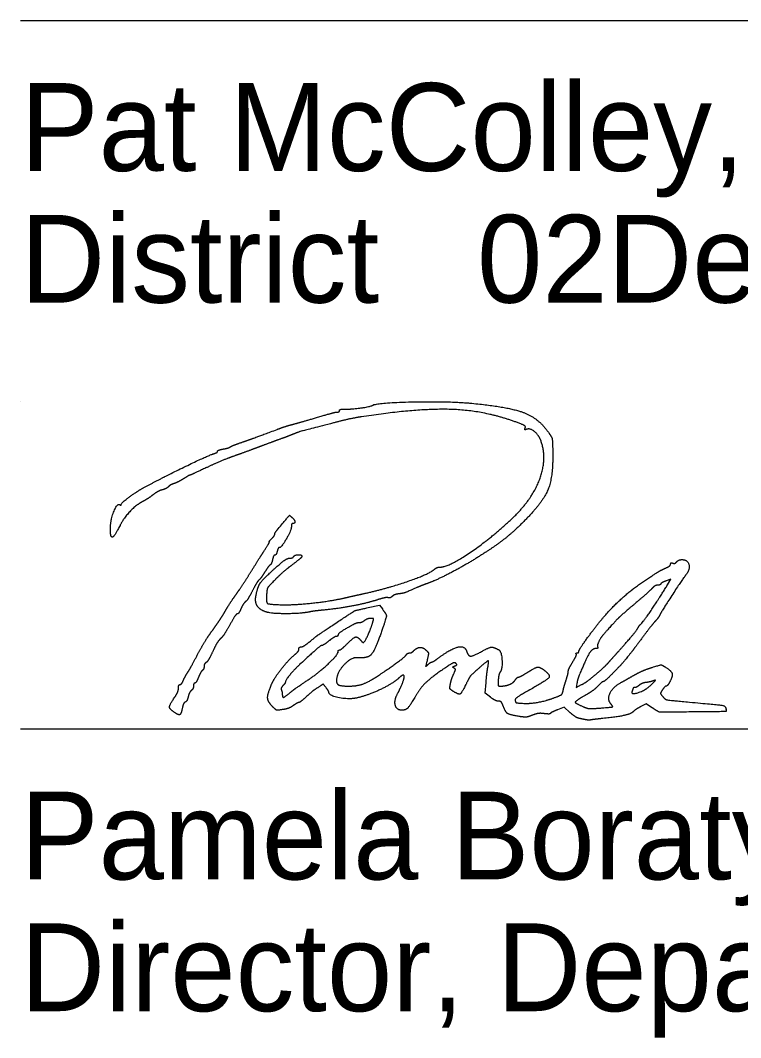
# Model space of a CAD drawing. Extents: x 0 to 42, y 0 to 22.
# Drawn here: x 24.528 to 25.676, y 7.305 to 8.926 of the extents above; entities that cross this region are included whole.
import ezdxf

# ---------------------------------------------------------------- set-up
doc = ezdxf.new("R2010")
doc.units = 0
doc.layers.add('SH_Data', color=7, linetype='Continuous')
doc.layers.add('SH_Text', color=7, linetype='Continuous')

msp = doc.modelspace()

# ---------------------------------------------------------------- linework, layer by layer
at = {"layer": 'SH_Data'}
for p, q in [((24.5279, 8.9262), (28.0279, 8.9262)), ((24.5279, 8.3191), (24.5279, 8.3191)), ((24.5279, 7.7968), (28.0279, 7.7968))]:
    msp.add_line(p, q, dxfattribs=at)
at = {"layer": 'SH_Text'}
for points in [[(25.5597, 8.0263), (25.5651, 8.0352), (25.5577, 8.0326)], [(25.0824, 7.9901), (25.1004, 7.9942), (25.1051, 7.988)], [(25.2773, 7.8473), (25.269, 7.8536), (25.2704, 7.8707)], [(25.4153, 7.8693), (25.4143, 7.8628), (25.4229, 7.8673)], [(25.5361, 7.83), (25.5255, 7.8368), (25.5171, 7.8323)], [(25.4043, 7.823), (25.3951, 7.8313), (25.3845, 7.8272)]]:
    msp.add_lwpolyline(points, dxfattribs=at)
for points in [[(25.033, 8.3018), (25.0351, 8.3018), (25.0368, 8.3029), (25.0368, 8.3043)], [(25.0368, 8.3043), (25.0368, 8.3056), (25.0408, 8.3066), (25.0458, 8.3065)], [(25.0458, 8.3065), (25.0554, 8.3062), (25.0864, 8.3106), (25.0898, 8.3127)], [(25.3205, 8.285), (25.2699, 8.304), (25.1619, 8.308), (25.0716, 8.2942)], [(25.0898, 8.3127), (25.0966, 8.3169), (25.2136, 8.3192), (25.248, 8.3158)], [(25.248, 8.3158), (25.3072, 8.31), (25.3548, 8.2917), (25.3706, 8.2686)], [(24.9612, 8.282), (24.9665, 8.2833), (24.9839, 8.2883), (25, 8.2931)], [(25, 8.2931), (25.0161, 8.2979), (25.031, 8.3018), (25.033, 8.3018)], [(25.0716, 8.2942), (25.0623, 8.2928), (25.0424, 8.2885), (25.0272, 8.2845)], [(24.8808, 8.2535), (24.8955, 8.2586), (24.9019, 8.261), (24.9372, 8.2741)], [(24.9372, 8.2741), (24.9451, 8.2771), (24.9559, 8.2806), (24.9612, 8.282)], [(25.0272, 8.2845), (24.9762, 8.2714), (24.9719, 8.2701), (24.9612, 8.2658)], [(25.3328, 8.2764), (25.3338, 8.2789), (25.3303, 8.2813), (25.3205, 8.285)], [(25.3352, 8.2743), (25.3326, 8.2733), (25.3319, 8.274), (25.3328, 8.2764)], [(25.3586, 8.2544), (25.3553, 8.2642), (25.3409, 8.2765), (25.3352, 8.2743)], [(24.9384, 8.2573), (24.9285, 8.2537), (24.9134, 8.2481), (24.9048, 8.2449)], [(24.9612, 8.2658), (24.9585, 8.2647), (24.9483, 8.2609), (24.9384, 8.2573)], [(25.3131, 8.1332), (25.344, 8.1627), (25.3679, 8.2262), (25.3586, 8.2544)], [(25.3706, 8.2686), (25.3755, 8.2614), (25.3764, 8.257), (25.3768, 8.2392)], [(24.837, 8.2357), (24.84, 8.2366), (24.8424, 8.2382), (24.8424, 8.2393)], [(24.8424, 8.2393), (24.8424, 8.2403), (24.8464, 8.242), (24.8514, 8.2429)], [(24.8514, 8.2429), (24.8563, 8.2438), (24.8615, 8.2454), (24.8628, 8.2464)], [(24.8628, 8.2464), (24.8641, 8.2473), (24.8722, 8.2506), (24.8808, 8.2535)], [(24.9048, 8.2449), (24.8962, 8.2416), (24.88, 8.2357), (24.8688, 8.2317)], [(25.3768, 8.2392), (25.3775, 8.1984), (25.3614, 8.1587), (25.332, 8.1288)], [(24.7248, 8.1814), (24.755, 8.1976), (24.8286, 8.2333), (24.837, 8.2357)], [(24.8688, 8.2317), (24.8576, 8.2278), (24.8372, 8.2192), (24.8236, 8.2127)], [(24.8236, 8.2127), (24.8099, 8.2063), (24.7983, 8.201), (24.7977, 8.201)], [(24.7877, 8.1953), (24.7828, 8.1922), (24.7761, 8.1888), (24.7729, 8.1878)], [(24.7977, 8.201), (24.7971, 8.201), (24.7927, 8.1984), (24.7877, 8.1953)], [(24.6888, 8.1547), (24.6888, 8.1569), (24.7142, 8.1757), (24.7248, 8.1814)], [(24.754, 8.1778), (24.7505, 8.1769), (24.7438, 8.1733), (24.7392, 8.1697)], [(24.7637, 8.1826), (24.7619, 8.1808), (24.7576, 8.1787), (24.754, 8.1778)], [(24.7729, 8.1878), (24.7697, 8.1868), (24.7655, 8.1844), (24.7637, 8.1826)], [(24.7233, 8.1594), (24.7129, 8.1541), (24.693, 8.1332), (24.6868, 8.1211)], [(24.7392, 8.1697), (24.7346, 8.1661), (24.7274, 8.1615), (24.7233, 8.1594)], [(24.6716, 8.1169), (24.6717, 8.1301), (24.6823, 8.1567), (24.6865, 8.1541)], [(24.6865, 8.1541), (24.6877, 8.1533), (24.6888, 8.1536), (24.6888, 8.1547)], [(24.939, 8.1158), (24.9575, 8.1379), (24.9568, 8.1374), (24.9609, 8.134)], [(24.9609, 8.134), (24.9652, 8.1304), (24.9661, 8.1242), (24.9624, 8.1242)], [(25.1964, 8.0546), (25.2105, 8.0546), (25.2786, 8.1005), (25.3131, 8.1332)], [(25.332, 8.1288), (25.3134, 8.1099), (25.281, 8.085), (25.2505, 8.0662)], [(24.673, 8.1032), (24.6722, 8.104), (24.6716, 8.1101), (24.6716, 8.1169)], [(24.6868, 8.1211), (24.6801, 8.1082), (24.6748, 8.1013), (24.673, 8.1032)], [(24.9336, 8.1072), (24.9336, 8.1084), (24.936, 8.1123), (24.939, 8.1158)], [(24.96, 8.1191), (24.96, 8.1135), (24.9441, 8.0858), (24.9409, 8.0858)], [(24.9624, 8.1242), (24.9611, 8.1242), (24.96, 8.1219), (24.96, 8.1191)], [(24.916, 8.0797), (24.9216, 8.0883), (24.9256, 8.0954), (24.925, 8.0954)], [(24.925, 8.0954), (24.9245, 8.0954), (24.9261, 8.0975), (24.9288, 8.1002)], [(24.9288, 8.1002), (24.9314, 8.1028), (24.9336, 8.1059), (24.9336, 8.1072)], [(24.894, 8.0447), (24.9006, 8.0553), (24.9105, 8.0711), (24.916, 8.0797)], [(24.9374, 8.0798), (24.9366, 8.0765), (24.9349, 8.0738), (24.9337, 8.0738)], [(24.9409, 8.0858), (24.9398, 8.0858), (24.9382, 8.0831), (24.9374, 8.0798)], [(24.9252, 8.0448), (24.9409, 8.0594), (24.9536, 8.069), (24.9576, 8.069)], [(24.93, 8.0666), (24.9291, 8.0626), (24.9274, 8.0588), (24.9261, 8.058)], [(24.9337, 8.0738), (24.9325, 8.0738), (24.9309, 8.0705), (24.93, 8.0666)], [(24.9576, 8.069), (24.9601, 8.069), (24.9628, 8.07), (24.9636, 8.0714)], [(24.9768, 8.0717), (24.9768, 8.0706), (24.97, 8.0647), (24.9618, 8.0586)], [(24.9636, 8.0714), (24.9654, 8.0743), (24.9768, 8.0746), (24.9768, 8.0717)], [(25.2505, 8.0662), (25.2313, 8.0543), (25.1901, 8.0333), (25.176, 8.0282)], [(25.5648, 8.0595), (25.5648, 8.061), (25.5663, 8.0617), (25.5682, 8.061)], [(25.5682, 8.061), (25.5701, 8.0602), (25.5729, 8.0612), (25.5745, 8.0631)], [(25.5745, 8.0631), (25.5761, 8.065), (25.5798, 8.0666), (25.5827, 8.0666)], [(25.5827, 8.0666), (25.5921, 8.0666), (25.5959, 8.0505), (25.5885, 8.0415)], [(24.8722, 8.0117), (24.8776, 8.0192), (24.8874, 8.034), (24.894, 8.0447)], [(24.9038, 8.0102), (24.9066, 8.0232), (24.9127, 8.0332), (24.9252, 8.0448)], [(24.9176, 8.0466), (24.9142, 8.0411), (24.9101, 8.0355), (24.9084, 8.0341)], [(24.9261, 8.058), (24.9248, 8.0572), (24.921, 8.0521), (24.9176, 8.0466)], [(24.9618, 8.0586), (24.9535, 8.0525), (24.941, 8.0416), (24.934, 8.0345)], [(25.0764, 8.0126), (25.1133, 8.0208), (25.1796, 8.0437), (25.1882, 8.0512)], [(25.1882, 8.0512), (25.1903, 8.0531), (25.1939, 8.0546), (25.1964, 8.0546)], [(25.528, 8.0362), (25.5469, 8.0484), (25.5488, 8.0495), (25.557, 8.0532)], [(25.557, 8.0532), (25.5613, 8.0551), (25.5648, 8.058), (25.5648, 8.0595)], [(24.9084, 8.0341), (24.9068, 8.0328), (24.9021, 8.0252), (24.8981, 8.0172)], [(24.934, 8.0345), (24.9233, 8.0235), (24.9211, 8.0199), (24.9206, 8.0116)], [(25.176, 8.0282), (25.1714, 8.0266), (25.1643, 8.0238), (25.1603, 8.022)], [(25.4334, 7.9437), (25.4556, 7.9745), (25.5007, 8.0185), (25.528, 8.0362)], [(25.549, 8.0279), (25.5483, 8.0267), (25.5459, 8.0258), (25.5437, 8.0258)], [(25.5885, 8.0415), (25.5843, 8.0365), (25.5515, 7.9861), (25.5483, 7.9799)], [(25.5577, 8.0326), (25.5537, 8.0312), (25.5498, 8.0291), (25.549, 8.0279)], [(24.8555, 7.9862), (24.8593, 7.9928), (24.8669, 8.0043), (24.8722, 8.0117)], [(24.8981, 8.0172), (24.8941, 8.0092), (24.889, 8.0012), (24.8868, 7.9994)], [(24.9206, 8.0116), (24.9197, 7.9982), (24.9238, 7.9953), (24.9444, 7.9947)], [(25.0428, 8.0051), (25.0507, 8.0069), (25.0658, 8.0103), (25.0764, 8.0126)], [(25.1318, 8.0121), (25.1279, 8.0117), (25.123, 8.0099), (25.121, 8.0081)], [(25.1603, 8.022), (25.1433, 8.0146), (25.1384, 8.0129), (25.1318, 8.0121)], [(25.5349, 8.0204), (25.5322, 8.0174), (25.5197, 8.0063), (25.5072, 7.9958)], [(25.5169, 7.9634), (25.5197, 7.9653), (25.5479, 8.0068), (25.5597, 8.0263)], [(25.5437, 8.0258), (25.5415, 8.0258), (25.5375, 8.0233), (25.5349, 8.0204)], [(24.8868, 7.9994), (24.8847, 7.9976), (24.8814, 7.9925), (24.8796, 7.9881)], [(24.9192, 7.9833), (24.9087, 7.9872), (24.9016, 7.9997), (24.9038, 8.0102)], [(24.9444, 7.9947), (24.9636, 7.9942), (25.0215, 8.0003), (25.0428, 8.0051)], [(25.0962, 8.0022), (25.0797, 7.9969), (25.0346, 7.9884), (25.0108, 7.9861)], [(25.1142, 8.0059), (25.1125, 8.0065), (25.1044, 8.0048), (25.0962, 8.0022)], [(25.121, 8.0081), (25.1189, 8.0063), (25.1158, 8.0053), (25.1142, 8.0059)], [(25.5072, 7.9958), (25.4876, 7.9793), (25.4759, 7.9679), (25.4592, 7.949)], [(24.8425, 7.9655), (24.8458, 7.9703), (24.8517, 7.9796), (24.8555, 7.9862)], [(24.8739, 7.9802), (24.8726, 7.9802), (24.8672, 7.9723), (24.8618, 7.9626)], [(24.8796, 7.9881), (24.8777, 7.9838), (24.8752, 7.9802), (24.8739, 7.9802)], [(24.9904, 7.9835), (24.9767, 7.9804), (24.9272, 7.9803), (24.9192, 7.9833)], [(25.0108, 7.9861), (25.0025, 7.9853), (24.9933, 7.9841), (24.9904, 7.9835)], [(25.0284, 7.9637), (25.06, 7.9847), (25.0614, 7.9854), (25.0824, 7.9901)], [(25.1051, 7.988), (25.1117, 7.9792), (25.1115, 7.9744), (25.1038, 7.9518)], [(25.5483, 7.9799), (25.5466, 7.9764), (25.5427, 7.971), (25.5397, 7.9678)], [(24.8289, 7.9463), (24.833, 7.9521), (24.8391, 7.9608), (24.8425, 7.9655)], [(24.8618, 7.9626), (24.8565, 7.9529), (24.8498, 7.9429), (24.847, 7.9404)], [(24.9892, 7.9358), (25.0029, 7.9468), (25.0009, 7.9455), (25.0284, 7.9637)], [(25.0581, 7.9626), (25.0436, 7.9547), (25.0344, 7.9483), (25.0344, 7.9463)], [(25.0678, 7.9658), (25.0656, 7.9658), (25.0612, 7.9643), (25.0581, 7.9626)], [(25.0765, 7.9693), (25.074, 7.9673), (25.07, 7.9658), (25.0678, 7.9658)], [(25.075, 7.9346), (25.0768, 7.9346), (25.0866, 7.9557), (25.0897, 7.9664)], [(25.0864, 7.9729), (25.0835, 7.9728), (25.0791, 7.9712), (25.0765, 7.9693)], [(25.0897, 7.9664), (25.0914, 7.9721), (25.091, 7.9729), (25.0864, 7.9729)], [(25.513, 7.9582), (25.5142, 7.9604), (25.5159, 7.9627), (25.5169, 7.9634)], [(25.5397, 7.9678), (25.5367, 7.9645), (25.5278, 7.9532), (25.5199, 7.9425)], [(24.81, 7.9142), (24.8163, 7.926), (24.8248, 7.9405), (24.8289, 7.9463)], [(25.0344, 7.9463), (25.0344, 7.9451), (25.0332, 7.9442), (25.0317, 7.9442)], [(25.1038, 7.9518), (25.0935, 7.9219), (25.0815, 7.9088), (25.0656, 7.9102)], [(25.4592, 7.949), (25.4533, 7.9424), (25.4471, 7.9295), (25.4485, 7.9271)], [(25.4817, 7.9204), (25.497, 7.9375), (25.5106, 7.9539), (25.513, 7.9582)], [(24.847, 7.9404), (24.8441, 7.9378), (24.8386, 7.9287), (24.8347, 7.9202)], [(24.9754, 7.9274), (24.9772, 7.9274), (24.9834, 7.9311), (24.9892, 7.9358)], [(25.02, 7.937), (25.015, 7.933), (25.01, 7.9298), (25.0088, 7.9297)], [(25.0317, 7.9442), (25.0303, 7.9442), (25.025, 7.9409), (25.02, 7.937)], [(25.0368, 7.9226), (25.0381, 7.9226), (25.0435, 7.9269), (25.0488, 7.9322)], [(25.0488, 7.9322), (25.0589, 7.9423), (25.0654, 7.9441), (25.0704, 7.9382)], [(25.0704, 7.9382), (25.072, 7.9362), (25.0741, 7.9346), (25.075, 7.9346)], [(25.4184, 7.9203), (25.4184, 7.9217), (25.4251, 7.9322), (25.4334, 7.9437)], [(25.5199, 7.9425), (25.512, 7.9319), (25.5043, 7.9217), (25.5029, 7.9199)], [(24.7946, 7.8866), (24.7968, 7.8899), (24.8037, 7.9023), (24.81, 7.9142)], [(24.8347, 7.9202), (24.8307, 7.9116), (24.826, 7.9037), (24.8242, 7.9026)], [(24.9285, 7.8679), (24.933, 7.8783), (24.9562, 7.9078), (24.9666, 7.9161)], [(24.9666, 7.9161), (24.9695, 7.9185), (24.972, 7.922), (24.972, 7.9239)], [(24.972, 7.9239), (24.972, 7.9258), (24.9735, 7.9274), (24.9754, 7.9274)], [(25.0088, 7.9297), (25.0069, 7.9297), (24.9985, 7.9225), (24.9732, 7.8992)], [(24.9883, 7.876), (25.0039, 7.8864), (25.0344, 7.9151), (25.0344, 7.9194)], [(25.0344, 7.9194), (25.0344, 7.9212), (25.0355, 7.9226), (25.0368, 7.9226)], [(25.1004, 7.8829), (25.119, 7.8953), (25.1414, 7.9119), (25.1431, 7.9147)], [(25.1431, 7.9147), (25.1442, 7.9164), (25.1465, 7.9178), (25.1483, 7.9178)], [(25.1483, 7.9178), (25.1501, 7.9178), (25.1534, 7.9195), (25.1555, 7.9217)], [(25.1555, 7.9217), (25.1605, 7.9266), (25.1705, 7.9267), (25.1754, 7.9217)], [(25.1754, 7.9217), (25.1786, 7.9186), (25.1788, 7.9161), (25.1767, 7.907)], [(25.1935, 7.9091), (25.2138, 7.9243), (25.2365, 7.9299), (25.2395, 7.9204)], [(25.2395, 7.9204), (25.2419, 7.9128), (25.25, 7.9127), (25.2633, 7.9201)], [(25.2633, 7.9201), (25.2752, 7.9267), (25.2825, 7.9274), (25.2907, 7.9228)], [(25.2907, 7.9228), (25.2951, 7.9203), (25.2967, 7.8923), (25.2928, 7.8872)], [(25.4086, 7.9035), (25.4125, 7.9097), (25.415, 7.9155), (25.4142, 7.9163)], [(25.4142, 7.9163), (25.4134, 7.9171), (25.414, 7.9178), (25.4156, 7.9178)], [(25.4156, 7.9178), (25.4171, 7.9178), (25.4184, 7.9189), (25.4184, 7.9203)], [(25.4462, 7.925), (25.4399, 7.925), (25.4304, 7.9098), (25.4183, 7.8806)], [(25.4485, 7.9271), (25.4493, 7.9259), (25.4482, 7.925), (25.4462, 7.925)], [(25.4661, 7.9029), (25.4692, 7.9065), (25.4762, 7.9143), (25.4817, 7.9204)], [(25.5029, 7.9199), (25.4896, 7.9034), (25.485, 7.8983), (25.4732, 7.8861)], [(24.8242, 7.9026), (24.8223, 7.9016), (24.8208, 7.8987), (24.8208, 7.8962)], [(24.9732, 7.8992), (24.9641, 7.8909), (24.9504, 7.8738), (24.9504, 7.8708)], [(25.0656, 7.9102), (25.0552, 7.9111), (25.032, 7.8857), (25.032, 7.8735)], [(25.1767, 7.907), (25.1744, 7.8967), (25.1745, 7.8962), (25.1783, 7.8997)], [(25.1783, 7.8997), (25.1805, 7.9017), (25.1832, 7.9034), (25.1841, 7.9034)], [(25.1841, 7.9034), (25.1851, 7.9034), (25.1893, 7.9059), (25.1935, 7.9091)], [(25.2222, 7.9013), (25.2204, 7.9031), (25.2145, 7.9003), (25.202, 7.8918)], [(25.2206, 7.8971), (25.2236, 7.8982), (25.224, 7.8995), (25.2222, 7.9013)], [(25.2734, 7.8956), (25.2752, 7.905), (25.2726, 7.9054), (25.2633, 7.8972)], [(25.4016, 7.8887), (25.4016, 7.8905), (25.4047, 7.8972), (25.4086, 7.9035)], [(25.446, 7.8841), (25.4539, 7.8909), (25.4629, 7.8994), (25.4661, 7.9029)], [(25.5353, 7.8948), (25.5493, 7.899), (25.5505, 7.899), (25.5564, 7.8952)], [(24.7877, 7.874), (24.7893, 7.8776), (24.7924, 7.8833), (24.7946, 7.8866)], [(24.8183, 7.8901), (24.8169, 7.8892), (24.8141, 7.8843), (24.812, 7.8792)], [(24.8208, 7.8962), (24.8208, 7.8937), (24.8197, 7.8909), (24.8183, 7.8901)], [(25.0519, 7.865), (25.065, 7.865), (25.0841, 7.872), (25.1004, 7.8829)], [(25.14, 7.8797), (25.14, 7.8827), (25.136, 7.8822), (25.1324, 7.8787)], [(25.202, 7.8918), (25.1823, 7.8784), (25.1651, 7.8613), (25.1568, 7.847)], [(25.2136, 7.8682), (25.2144, 7.8723), (25.2166, 7.8794), (25.2187, 7.8838)], [(25.2194, 7.8936), (25.2172, 7.895), (25.2175, 7.8959), (25.2206, 7.8971)], [(25.2187, 7.8838), (25.2215, 7.8901), (25.2217, 7.8922), (25.2194, 7.8936)], [(25.2633, 7.8972), (25.2474, 7.8832), (25.2437, 7.8788), (25.2382, 7.8674)], [(25.2704, 7.8707), (25.2712, 7.8801), (25.2726, 7.8913), (25.2734, 7.8956)], [(25.2928, 7.8872), (25.2916, 7.8855), (25.2903, 7.8798), (25.2899, 7.8746)], [(25.3224, 7.8794), (25.3236, 7.8794), (25.3297, 7.8826), (25.336, 7.8866)], [(25.3642, 7.8895), (25.3739, 7.8819), (25.367, 7.874), (25.3354, 7.8563)], [(25.336, 7.8866), (25.3489, 7.8948), (25.3565, 7.8956), (25.3642, 7.8895)], [(25.3981, 7.8746), (25.4, 7.8805), (25.4016, 7.8869), (25.4016, 7.8887)], [(25.4229, 7.8673), (25.4277, 7.8697), (25.4381, 7.8773), (25.446, 7.8841)], [(25.4732, 7.8861), (25.4657, 7.8784), (25.4586, 7.8722), (25.4576, 7.8722)], [(25.4864, 7.8711), (25.4893, 7.8726), (25.4981, 7.8776), (25.506, 7.8821)], [(25.506, 7.8821), (25.5139, 7.8866), (25.5271, 7.8923), (25.5353, 7.8948)], [(25.5564, 7.8952), (25.566, 7.8889), (25.5684, 7.8815), (25.5638, 7.8725)], [(24.78, 7.8617), (24.78, 7.8648), (24.7811, 7.8674), (24.7824, 7.8674)], [(24.7824, 7.8674), (24.7838, 7.8674), (24.7862, 7.8703), (24.7877, 7.874)], [(24.804, 7.8653), (24.804, 7.8628), (24.8024, 7.8595), (24.8005, 7.8579)], [(24.8061, 7.8698), (24.8049, 7.8698), (24.804, 7.8677), (24.804, 7.8653)], [(24.812, 7.8792), (24.81, 7.874), (24.8073, 7.8698), (24.8061, 7.8698)], [(24.9302, 7.8322), (24.9225, 7.8398), (24.9219, 7.8526), (24.9285, 7.8679)], [(24.9466, 7.8657), (24.9446, 7.8636), (24.9435, 7.8604), (24.9442, 7.8585)], [(24.9504, 7.8708), (24.9504, 7.87), (24.9487, 7.8677), (24.9466, 7.8657)], [(24.9568, 7.8536), (24.9643, 7.8597), (24.9696, 7.8635), (24.9883, 7.876)], [(25.0154, 7.8624), (25.0109, 7.8682), (25.0108, 7.8682), (25.0041, 7.8638)], [(25.032, 7.8735), (25.032, 7.8683), (25.0398, 7.865), (25.0519, 7.865)], [(25.1324, 7.8787), (25.1228, 7.8696), (25.084, 7.8508), (25.0656, 7.8463)], [(25.1294, 7.853), (25.1335, 7.8606), (25.14, 7.8769), (25.14, 7.8797)], [(25.2182, 7.8566), (25.2132, 7.8599), (25.2124, 7.8619), (25.2136, 7.8682)], [(25.2382, 7.8674), (25.2315, 7.8537), (25.2267, 7.8511), (25.2182, 7.8566)], [(25.2899, 7.8746), (25.2894, 7.867), (25.2901, 7.865), (25.2932, 7.865)], [(25.2932, 7.865), (25.3016, 7.865), (25.3136, 7.8698), (25.3168, 7.8745)], [(25.3168, 7.8745), (25.3187, 7.8772), (25.3212, 7.8794), (25.3224, 7.8794)], [(25.3933, 7.8575), (25.394, 7.8609), (25.3961, 7.8686), (25.3981, 7.8746)], [(25.4183, 7.8806), (25.4172, 7.8779), (25.4159, 7.8728), (25.4153, 7.8693)], [(25.449, 7.8652), (25.4454, 7.8614), (25.4373, 7.8553), (25.431, 7.8516)], [(25.4576, 7.8722), (25.4565, 7.8722), (25.4526, 7.869), (25.449, 7.8652)], [(25.4694, 7.8367), (25.4633, 7.8441), (25.4731, 7.8639), (25.4864, 7.8711)], [(25.5033, 7.8568), (25.5008, 7.8503), (25.5263, 7.8593), (25.5348, 7.8679)], [(25.5144, 7.8662), (25.5122, 7.8642), (25.5091, 7.8626), (25.5076, 7.8626)], [(25.5254, 7.8707), (25.5215, 7.8702), (25.5166, 7.8681), (25.5144, 7.8662)], [(25.5372, 7.8734), (25.5345, 7.8724), (25.5292, 7.8712), (25.5254, 7.8707)], [(25.5348, 7.8679), (25.5403, 7.8735), (25.5408, 7.8748), (25.5372, 7.8734)], [(25.5638, 7.8725), (25.5616, 7.8683), (25.5589, 7.865), (25.5578, 7.865)], [(24.7742, 7.8475), (24.7774, 7.8522), (24.78, 7.8586), (24.78, 7.8617)], [(24.8005, 7.8579), (24.7986, 7.8563), (24.7964, 7.8518), (24.7955, 7.8478)], [(24.9442, 7.8585), (24.945, 7.8565), (24.9456, 7.8534), (24.9456, 7.8516)], [(24.9456, 7.8516), (24.9456, 7.8467), (24.949, 7.8473), (24.9568, 7.8536)], [(25.0041, 7.8638), (24.9959, 7.8584), (24.9933, 7.8564), (24.9821, 7.8464)], [(25.0199, 7.855), (25.0199, 7.8559), (25.0179, 7.8592), (25.0154, 7.8624)], [(25.0656, 7.8463), (25.0527, 7.8433), (25.0201, 7.8494), (25.0199, 7.855)], [(25.1361, 7.8266), (25.1277, 7.8266), (25.1237, 7.8424), (25.1294, 7.853)], [(25.3354, 7.8563), (25.3222, 7.8488), (25.316, 7.844), (25.3168, 7.8418)], [(25.3806, 7.8469), (25.3894, 7.8502), (25.3923, 7.8527), (25.3933, 7.8575)], [(25.431, 7.8516), (25.4131, 7.8412), (25.412, 7.8379), (25.425, 7.8324)], [(25.5048, 7.8616), (25.5048, 7.861), (25.5041, 7.8589), (25.5033, 7.8568)], [(25.5076, 7.8626), (25.506, 7.8626), (25.5048, 7.8621), (25.5048, 7.8616)], [(25.5519, 7.8591), (25.5484, 7.8538), (25.5484, 7.8529), (25.5523, 7.8482)], [(25.5578, 7.865), (25.5567, 7.865), (25.554, 7.8623), (25.5519, 7.8591)], [(24.7725, 7.8238), (24.7655, 7.8286), (24.7659, 7.8354), (24.7742, 7.8475)], [(24.7908, 7.8394), (24.7891, 7.8388), (24.787, 7.8346), (24.7862, 7.8302)], [(24.7955, 7.8478), (24.7946, 7.8439), (24.7925, 7.8401), (24.7908, 7.8394)], [(24.9629, 7.8338), (24.9593, 7.8312), (24.9519, 7.8284), (24.9464, 7.8276)], [(24.9714, 7.8386), (24.9703, 7.8386), (24.9665, 7.8364), (24.9629, 7.8338)], [(24.9821, 7.8464), (24.9773, 7.8421), (24.9725, 7.8386), (24.9714, 7.8386)], [(25.1568, 7.847), (25.1486, 7.8329), (25.1422, 7.8266), (25.1361, 7.8266)], [(25.2903, 7.841), (25.2877, 7.841), (25.2819, 7.8438), (25.2773, 7.8473)], [(25.2978, 7.8332), (25.296, 7.8383), (25.2934, 7.841), (25.2903, 7.841)], [(25.3232, 7.8166), (25.3082, 7.819), (25.3013, 7.8235), (25.2978, 7.8332)], [(25.3168, 7.8418), (25.3181, 7.8384), (25.3188, 7.8382), (25.3308, 7.8375)], [(25.3308, 7.8375), (25.3413, 7.8369), (25.3674, 7.8418), (25.3806, 7.8469)], [(25.4518, 7.8299), (25.4713, 7.8315), (25.4731, 7.8322), (25.4694, 7.8367)], [(25.5523, 7.8482), (25.5559, 7.8437), (25.5609, 7.8427), (25.5948, 7.8395)], [(25.5948, 7.8395), (25.6439, 7.835), (25.6521, 7.8334), (25.6531, 7.8287)], [(24.7862, 7.8302), (24.7843, 7.8205), (24.7801, 7.8185), (24.7725, 7.8238)], [(24.9464, 7.8276), (24.9377, 7.8262), (24.9355, 7.8268), (24.9302, 7.8322)], [(25.3443, 7.8186), (25.3373, 7.8158), (25.3318, 7.8153), (25.3232, 7.8166)], [(25.3632, 7.8211), (25.3574, 7.8219), (25.3501, 7.8209), (25.3443, 7.8186)], [(25.3733, 7.8215), (25.3729, 7.8206), (25.3683, 7.8204), (25.3632, 7.8211)], [(25.3845, 7.8272), (25.3787, 7.8249), (25.3737, 7.8224), (25.3733, 7.8215)], [(25.4189, 7.8135), (25.4159, 7.8142), (25.4093, 7.8184), (25.4043, 7.823)], [(25.425, 7.8324), (25.4318, 7.8294), (25.4383, 7.8289), (25.4518, 7.8299)], [(25.5054, 7.8244), (25.5017, 7.8207), (25.4802, 7.8158), (25.4568, 7.8134)], [(25.5171, 7.8323), (25.5125, 7.8298), (25.5072, 7.8263), (25.5054, 7.8244)], [(25.5828, 7.8236), (25.5471, 7.8232), (25.5467, 7.8232), (25.5361, 7.83)], [(25.6531, 7.8287), (25.6539, 7.8244), (25.6519, 7.8243), (25.5828, 7.8236)], [(25.4292, 7.8114), (25.4265, 7.8119), (25.4219, 7.8129), (25.4189, 7.8135)], [(25.4376, 7.8111), (25.4356, 7.8107), (25.4318, 7.8108), (25.4292, 7.8114)], [(25.4568, 7.8134), (25.4482, 7.8125), (25.4396, 7.8115), (25.4376, 7.8111)]]:
    msp.add_open_spline(points, degree=2, dxfattribs=at)

# ---------------------------------------------------------------- texts
for s, p in [('Pat McColley, P.E., S.I.', (24.5279, 8.6862)), ('District       Deputy Director', (24.5279, 8.4762)), ('              02', (24.5279, 8.4762)), ('Pamela Boratyn', (24.5279, 7.5568)), ('Director, Department of Transportation', (24.5279, 7.3468))]:
    msp.add_text(s, height=0.14, dxfattribs=at).set_placement(p)

doc.saveas('drawing.dxf')
